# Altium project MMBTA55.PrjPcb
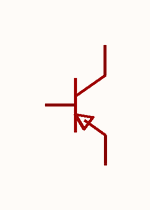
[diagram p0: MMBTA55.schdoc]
1 sheet, 1 parts. Net scope: global (net labels, ports and power ports of the same name join across sheets).

## Sheet MMBTA55.schdoc
size 127 x 101 mm

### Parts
Q?  mmbta55(range:100-400)  [SOT-23-3_L2.9-W1.6-P1.90-LS2.8-BR]  (value not drawn)

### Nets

Not connected (* = marked no-connect by the designer): Q? 1(B) 2(E) 3(C)

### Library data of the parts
Q? = mmbta55(range:100-400): 晶体管类型:PNP;集电极电流(Ic):500mA;集射极击穿电压(Vceo):60V;耗散功率(Pd):225mW;直流电流增益(hFE):100;; Manufacturer: CJ(江苏长电/长晶); AddInBom: yes; ModelId: 89cb27a44ab2466697082bb9fd73a7d0; ModelName: SOT-23-3L_L2.9-W1.6-H1.1-LS2.8-P0.95; ModelTransform: 114.173,110.236,0,90,0,0,0,0,0; type: PNP; Current - Collector(Ic): 500mA; Collector - Emitter Voltage VCEO: 60V; Pd - Power Dissipation: 225mW; DC Current Gain: 100; Transition frequency(fT): 50MHz; Current - Collector Cutoff: 100nA; Vce Saturation(VCE(sat)): 250mV; Emitter-Base Voltage(Vebo): 4V; Number: 1个PNP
